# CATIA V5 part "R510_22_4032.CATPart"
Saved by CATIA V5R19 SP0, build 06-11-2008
Part number: Frez_trzpieniowo_walcowy_TYP_S
Material "Steel": density 7860 kg/m3, Young's modulus 2e+11 Pa, Poisson ratio 0.266, thermal expansion 1.17e-05 1/K
Bounding box of the stored display mesh (mm): x -18.999 to 18.999, y -18.999 to 18.999, z 0 to 110
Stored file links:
  G:\Podręcznik\catia\tools\CATPart\7.CATPart
  C:\Program Files\Dassault Systemes\B19\intel_a\startup\materials\Catalog.CATMaterial
  F:\OSTATNIE\DesignTable2.xls
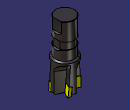
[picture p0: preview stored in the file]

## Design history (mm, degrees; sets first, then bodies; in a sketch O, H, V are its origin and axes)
Parameters
  CuttingType = "CUTTER"
  d = 32 mm {design table}
  D = 40 mm {design table}
  L = 110 mm {design table}
  l = 60 mm {design table}
  alfa = 11 deg {design table}
  gammap = 4 deg {design table}
  S = 4.76 mm {design table}
  epsilon = 85 deg {design table}
  lp = 16 mm {design table}
  x = 0.591 mm {design table}
  gammaf = -10 deg {design table}
  z = 4 {design table}
  teta = 90 deg {design table}
  `lp'` = 15.961 mm {design table}
  `lp''` = 9.4182 mm {design table}
Body1 "BODY" (main body), material "Steel"
  Sketch1 "sketch" on yz-plane, origin (0, 0, 0), H (0, 1, 0), V (0, 0, 1)
    line L1 (0, 3.0466) -> (19, 0.7137)
    line L2 (19, 0.7137) -> (19, 50)
    point P3 (19, 50)
    line L3 (19, 50) -> (19, 50)
    point P4 (16, 50)
    line L4 (16, 51.99) -> (16, 68)
    point P5 (16, 68)
    line L5 (16, 68) -> (15, 68)
    line L6 (15, 68) -> (15, 80)
    line L7 (15, 80) -> (16, 80)
    point P8 (16, 80)
    line L8 (16, 80) -> (16, 109.2929)
    line L9 (16, 109.2929) -> (15.2929, 110)
    line L10 (15.2929, 110) -> (0, 110)
    point P11 (0, 110)
    line L11 (0, 110) -> (0, 3.0466)
    construction line L12 (0, -29.1199) -> (0, 199.3445)
    point P12 (0, -29.1199)
    construction line L13 (0, 0.591) -> (20, 0.591)
    point P14 (0, 0.591)
    point P15 (20, 0.591)
    construction line L14 (0, 3.0466) -> (20, 0.591)
    axis line L15 (20, 0.591) -> (20, -5.0846)
    line L16 (19, 50) -> (16, 51.99)
    point P17 (19, 50)
    length L6 = 12 {= 0.2*l}
    distance P3 H = 50 {= L-l}
    length L9 = 1
    angle L8 L9 = 45
    distance L6 L8 = 1
    distance L8 L11 = 16 {= d/2}
    length L13 = 20 {= D/2}
    distance H L13 = 0.591 {= x}
    distance L10 L7 = 30 {= 0.5*l}
    distance P15 L2 = 1
    distance P4 P5 = 18 {= 0.3*l}
    length L16 = 3.6 {= 0.2*(0.3*l)}
    angle L1 L2 = 83
    vertical: L2 V, L4 V, L6 V, L8 V, L11 V, L12 V, L15 V
    horizontal: L3 H, L5 H, L7 H, L10 H, L13 H
    coincidence: P8 L4, P11 V, P12 V, L1 L14, P14 L12, L3 P4, L4 P4, P3 P17
  Shaft1: profile Sketch1, axis Z axis, angle 360
  Fillet1: radius 2 {= 0.1*D/2}, on edge [face of Shaft1 from Sketch1.L1 | face of Shaft1 from Sketch1.L2]
  Sketch2 on zx-plane, origin (0, 0, 0), H (-1, 0, 0), V (0, 0, 1)
    line L1 (-14, 110) -> (-14, 92)
    line L2 (-14, 92) -> (-16, 90)
    line L3 (-16, 90) -> (-16, 82)
    line L4 (-16, 82) -> (-14, 80)
    point P5 (-14, 80)
    line L5 (-14, 80) -> (-14, 68)
    line L6 (-14, 68) -> (-16, 66)
    point P7 (-16, 66)
    line L7 (-16, 66) -> (-16, 66)
    line L8 (-16, 66) -> (-19, 66)
    line L9 (-19, 66) -> (-19, 110)
    line L10 (-19, 110) -> (-14, 110)
    reference projected line E1 through (0, 0) direction (0, 1) from axis of face of Shaft1 from Sketch1.L8
    reference projected line E2 (-9.2929, 110) -> (9.2929, 110) from edge [face of Shaft1 from Sketch1.L9 | face of Shaft1 from Sketch1.L10]
    distance L3 E1 = 16 {= d/2}
    distance L1 L3 = 2
    angle L2 L3 = 45
    angle L4 L3 = 45
    length L5 = 12 {= l*0.2}
    length L1 = 18 {= 0.3*l}
    distance P5 L10 = 30 {= 0.5*l}
    distance L9 L1 = 5
    distance L7 L5 = 2
    angle L5 L6 = 45
    vertical: L1 V, L3 V, L5 V, L7 V, L9 V
    horizontal: L8 H, L10 H
    coincidence: L10 E2, L1 L5, P7 L8
  Pocket1: profile Sketch2, direction (0, -1, 0), length 8, mirrored extent
  Plane1: type Angle, Angle 150, Direction Z axis, RefPlane yz-plane
  Plane2: type Offset, Offset 1, RefPlane Plane1, reversed
  Sketch3 "gammap_os_obrotu" on Plane2, origin (0.866, -0.5, 0), H (-0.5, -0.866, 0), V (0, 0, 1)
    line L1 (1.3076, 0) -> (-0.9434, 0)
    reference intersected line E1 through (0, 0) direction (-1, 0) from xy-plane
    horizontal: L1 H
    coincidence: E1 L1
  Plane3 "gammap": type Angle, Angle -4 {= -gammap}, Direction Sketch3, RefPlane Plane2
  Plane4: type Offset, Offset 0.5, RefPlane Plane3, reversed
  Sketch4 on Plane4, origin (1.2859, -0.7424, 0.2345), H (-0.5, -0.866, 0), V (-0.0604, 0.0349, 0.9976)
    line L1 (-20, -2.3223) -> (-20, 6.2448)
    distance V L1 = 20 {= D/2}
  Plane5 "gammaf": type Angle, Angle 10 {= -gammaf}, Direction Sketch4, RefPlane Plane4
  Plane6: type Offset, Offset 0.5, RefPlane Plane5
  Plane7: type Angle, Angle 90, Direction Sketch4, RefPlane Plane5
  Sketch5 on Plane7, origin (6.1561, 18.4373, -0.5649), H (0.9396, -0.3424, 0.0007), V (0.0035, 0.0116, 0.9999)
    point P1 (5.4728, 0.561)
    line L1 (5.4728, 0.561) -> (0.661, 1.1605)
    line L2 (0.661, 1.1605) -> (-0.3008, 15.2773)
    line L3 (-0.3008, 15.2773) -> (4.3853, 16.524)
    line L4 (4.3853, 16.524) -> (5.4728, 0.561)
    reference projected line E1 (5.6139, -1.5097) -> (5.0316, 7.0376) from Sketch4
    construction line L5 (4.3853, 16.524) -> (-0.5643, 16.1867)
    axis line L6 (5.4728, 0.561) -> (1.7473, 0.3071)
    reference intersected line E2 through (0, 0.565) direction (-1, 0.0007) from xy-plane
    distance L2 L4 = 4.76 {= S}
    length L4 = 16 {= lp}
    angle L5 L3 = 11 {= alfa}
    angle L6 L1 = 11 {= alfa}
    coincidence: L4 E1, P1 E2
    perpendicularity: L5 L2
    parallelism: L6 L5
  Plane8: type Offset, Offset 20 {= D/2}, RefPlane Plane1, reversed
  Sketch6 on Plane8, origin (17.3205, -10, 0), H (-0.5, -0.866, 0), V (0, 0, 1)
    line L1 (-9.6396, -3) -> (-9.6396, 35.1125)
    arc A1 centre (-21.6396, 35.1125) radius 12 from (-9.6396, 35.1125) to (-20, 47) ccw
    point P4 (-20, 47)
    line L2 (-20, 47) -> (-20, -3)
    point P5 (-20, -3)
    line L3 (-20, -3) -> (-9.6396, -3)
    axis line L4 (-20, -3) -> (-9.6396, -2.0936)
    point P6 (-20, -3)
    point P7 (-9.6396, -2.0936)
    reference projected line E1 (-9, 50) -> (9, 50) from edge [face of Shaft1 from Sketch1.L2 | face of Shaft1 from Sketch1.L16]
    distance L2 V = 20 {= D/2}
    angle L4 L2 = 85 {= epsilon}
    distance E1 P4 = 3
    radius A1 = 12
    distance H L3 = 3
    length L4 = 10.4 {= 0.65*lp}
    vertical: L1 V, L2 V
    horizontal: L3 H
    tangency: L1 A1
    coincidence: P6 P5, P7 L1
  Pocket2: profile Sketch6, direction (-0.866, 0.5, 0), up to Plane6
  CircPattern1: of Pocket2, instances 4 {= z}, angular step 90 {= teta}, axis from Z axis
  Sketch7 on Plane5, origin (4.6728, -1.5116, 0.7463), H (-0.3414, -0.9399, -0.0041), V (-0.066, 0.0196, 0.9976)
    line L1 (-19.5145, 15.1706) -> (-9.9659, 16.1626)
    point P1 (-19.5145, 15.1706)
    reference projected point E1 (-19.5145, 15.1706) from vertex [element of Sketch5 | element of Sketch5]
    reference projected line E2 (-19.2496, -1.1279) -> (-19.4121, 8.8708) from Sketch5.L4
    length L1 = 9.6 {= 0.6*lp}
    angle E2 L1 = 85 {= epsilon}
    coincidence: P1 E1
  Slot1: profile Sketch5, centre curve Sketch7
  CircPattern2: of Slot1, instances 4 {= z}, angular step 90 {= teta}, axis from Z axis
Body2 "INSERTS"
  Sketch8 "CUT" on yz-plane, origin (0, 0, 0), H (0, 1, 0), V (0, 0, 1)
    line L1 (10.6177, 0.8208) -> (20, 0)
    point P2 (20, 0)
    line L2 (20, 0) -> (20, 15.961)
    line L3 (20, 15.961) -> (10.6177, 16.7819)
    line L4 (10.6177, 16.7819) -> (10.6177, 0.8208)
    angle L3 L4 = 85
    length L2 = 15.961 {= `lp'`}
    length L1 = 9.4182 {= `lp''`}
    distance L2 V = 20 {= D/2}
    vertical: L2 V, L4 V
    parallelism: L3 L1
    coincidence: P2 H
  Sketch9 "NOCUT" on yz-plane, origin (0, 0, 0), H (0, 1, 0), V (0, 0, 1)
    axis line L1 (20, 0) -> (0, 1.7498)
    point P1 (0, 1.7498)
    point P2 (20, 0)
    reference projected line E1 (4.0988, 1.3912) -> (10.076, 0.8682) from Sketch8.L1
    reference projected point E2 (20, 0) from vertex [element of Sketch8 | element of Sketch8]
    line L2 (0, 1.7498) -> (10.6177, 0.8208)
    point P3 (10.6177, 0.8208)
    line L3 (10.6177, 0.8208) -> (10.6177, 16.7819)
    line L4 (10.6177, 16.7819) -> (19, 16.0485)
    line L5 (19, 16.0485) -> (19, 50)
    line L6 (19, 50) -> (16, 50)
    line L7 (16, 50) -> (16, 68)
    line L8 (16, 68) -> (15, 68)
    line L9 (15, 68) -> (15, 80)
    line L10 (15, 80) -> (16, 80)
    point P11 (16, 80)
    line L11 (16, 80) -> (16, 109.2929)
    point P12 (16, 110)
    line L12 (15.2929, 110) -> (0, 110)
    point P13 (0, 110)
    line L13 (0, 110) -> (0, 1.7498)
    line L14 (16, 109.2929) -> (15.2929, 110)
    length L9 = 12 {= 0.2*l}
    length L7 = 18 {= 0.3*l}
    distance L6 H = 50 {= L-l}
    distance L11 L13 = 16 {= d/2}
    distance L9 L11 = 1
    distance P3 P2 = 9.4182 {= `lp''`}
    distance L9 L7 = 1
    distance L5 P2 = 1
    length L3 = 15.961 {= `lp'`}
    angle L10 L9 = 90
    distance P11 P12 = 30 {= 0.5*l}
    angle L11 L14 = 45
    length L14 = 1
    coincidence: P1 V, L1 E1, P2 E2, P13 V, L11 P12, L12 P12
    parallelism: L2 L1, L4 L1
    vertical: L3 V, L5 V, L7 V, L9 V, L11 V, L13 V
    horizontal: L6 H, L8 H, L12 H
  Sketch10 on Plane7, origin (6.1561, 18.4373, -0.5649), H (0.9396, -0.3424, 0.0007), V (0.0035, 0.0116, 0.9999)
    point P1 (5.4728, 0.561)
    line L1 (5.4728, 0.561) -> (0.661, 1.1605)
    line L2 (0.661, 1.1605) -> (-0.3008, 15.2773)
    line L3 (-0.3008, 15.2773) -> (4.3853, 16.524)
    line L4 (4.3853, 16.524) -> (5.4728, 0.561)
    reference intersected line E1 through (5.4561, 0.8073) direction (0.068, -0.9977) from Plane5
    reference intersected line E2 through (0, 0.565) direction (-1, 0.0007) from xy-plane
    construction line L5 (4.3853, 16.524) -> (-6.5695, 15.7776)
    axis line L6 (5.4728, 0.561) -> (-1.2013, 0.1063)
    distance L2 L4 = 4.76 {= S}
    length L4 = 16 {= lp}
    angle L3 L5 = 11 {= alfa}
    angle L6 L1 = 11 {= alfa}
    coincidence: L4 E1, E2 P1
    perpendicularity: L5 L2
    parallelism: L6 L5
  Sketch11 on Plane5, origin (4.6728, -1.5116, 0.7463), H (-0.3414, -0.9399, -0.0041), V (-0.066, 0.0196, 0.9976)
    line L1 (-19.5145, 15.1706) -> (-9.9659, 16.1626)
    point P1 (-19.5145, 15.1706)
    reference projected point E1 (-19.5145, 15.1706) from vertex [element of Sketch10 | element of Sketch10]
    reference projected line E2 (-19.2546, -0.816) -> (-19.4172, 9.1826) from Sketch10.L4
    angle L1 E2 = 85 {= epsilon}
    length L1 = 9.6 {= 0.6*lp}
    coincidence: P1 E1
  Rib1: profile Sketch10, centre curve Sketch11
  CircPattern3: of the body so far, instances 4 {= z}, angular step 90 {= teta}, axis from Z axis
  Sketch12 on face of Rib1, origin (0.2242, 0.2239, 2.4875), H (0.7983, -0.5955, -0.09), V (-0.5837, -0.8018, 0.1281)
    point P1 (-0.6694, -19.8899)
    line L1 (-0.6694, -19.8899) -> (-5.0602, -17.5917)
    line L2 (-5.0602, -17.5917) -> (-5.3158, -18.5023)
    point P3 (-5.3158, -18.5023)
    line L3 (-5.3158, -18.5023) -> (-0.6694, -19.8899)
    reference projected point E1 (-0.6694, -19.8899) from vertex [face of Rib1 | face of Rib1 | face of Rib1]
    reference projected line E2 (-5.5799, -18.4235) -> (-2.4758, -19.3504) from edge [face of Rib1 | face of Rib1]
    reference projected point E3 (-5.3158, -18.5023) from vertex [face of Rib1 | face of Rib1 | face of Rib1]
    reference projected line E4 (-2.6566, -9.0259) -> (-1.0355, -3.249) from edge [face of Rib1 | face of Rib1]
    angle L1 L3 = 11
    coincidence: E1 P1, L3 E2, P3 E3, L2 E4
  Pocket3: profile Sketch12, direction along edge [face of Rib1 | face of Rib1], length 16 {= lp}
  CircPattern4: of Pocket3, instances 4 {= z}, angular step 90 {= teta}, axis from Z axis
Relations
  design table, configuration 7, drives d, D, L, l, alfa, gammap, S, epsilon, lp, x, gammaf, z, teta, `lp'`, `lp''`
